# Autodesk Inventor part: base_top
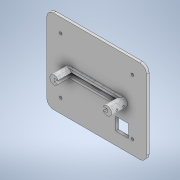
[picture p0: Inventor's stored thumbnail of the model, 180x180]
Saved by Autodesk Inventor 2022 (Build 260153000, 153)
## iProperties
Created: 2022-12
Part Number: base_top
Material: Generic
Document SubType Name: Modeling
Designer: suerfu
Density: 1 g/cm^3
Appearance: Default
Author: suerfu
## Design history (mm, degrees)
sketch "Sketch1"
  geometry: L1 (-47.625, 40.005)-(47.625, 40.005); L2 (47.625, 40.005)-(47.625, -40.005); L3 (47.625, -40.005)-(-47.625, -40.005); L4 (-47.625, -40.005)-(-47.625, 40.005); L5 (18.288, -15.748)-(30.48, -15.748); L6 (30.48, -15.748)-(30.48, -27.94); L7 (30.48, -27.94)-(18.288, -27.94); L8 (18.288, -27.94)-(18.288, -15.748); 1 further point
  constraints: 16 end point, 4 parallel, 2 horizontal, 2 perpendicular
  dimensions: "d0" = 95.25 distance of L2.end L3.end; "d1" = 80.01 distance of L3.end L1.start; "d29" = 47.625 distance from line of L4 point (0, 0) (= 0.5 x d0); "d30" = 40.005 distance from line of L3 point (0, 0) (= 0.5 x d1); "d42" = 18.288 distance from line of point (0, 0) L8; "d43" = 30.48 distance from line of point (0, 0) L6; "d44" = 15.748 distance from line of point (0, 0) L5; "d45" = 27.94 distance from line of L7 point (0, 0)
extrude "Extrusion1" new body sketch "Sketch1" distance "d26" = 2.54; taper "d27" = 0 deg
fillet "Fillet1" dims "d28" = 6.35
sketch "Sketch2"
  geometry: 5 further points
  constraints: 2 horizontal alignment, 2 vertical alignment
  dimensions: "d38" = 68.58 distance of point (34.29, 26.67) point (-34.29, 26.67); "d39" = 53.34 distance of point (-34.29, -26.67) point (-34.29, 26.67); "d40" = 34.29 horizontal distance of point (0, 0) point (-34.29, 26.67) (= 0.5 x d38); "d41" = 26.67 vertical distance of point (0, 0) point (-34.29, 26.67) (= 0.5 x d39)
hole "Hole1" sketch "Sketch2" at (-34.29, 26.67), (34.29, 26.67), (34.29, -26.67), (-34.29, -26.67) diameter "d31" = 2.4384; stored, may be unused: countersink angle "d35" = 82 deg, drill point angle "d37" = 118 deg; dims "d32" = 19.05, "d33" = 4.3688, "d34" = 6.35, "d36" = 12.7
sketch "Sketch3"
  geometry: L1 (-25.362, 1.626)-(-15.735, 1.626); L2 (-15.735, 1.626)-(-15.735, -1.626); L3 (-15.735, -1.626)-(-25.362, -1.626); L4 (-25.362, -1.626)-(-25.362, 1.626); L5 (-3.848, 1.626)-(3.848, 1.626); L6 (3.848, 1.626)-(3.848, -1.626); L7 (3.848, -1.626)-(-3.848, -1.626); L8 (-3.848, -1.626)-(-3.848, 1.626); L9 (15.735, 1.626)-(25.362, 1.626); L10 (25.362, 1.626)-(25.362, -1.626); L11 (25.362, -1.626)-(15.735, -1.626); L12 (15.735, -1.626)-(15.735, 1.626); L13 (-15.735, 0.909)-(15.735, 0.909); L14 (15.735, 0.909)-(15.735, -0.852); L15 (15.735, -0.852)-(-15.735, -0.852); L16 (-15.735, -0.852)-(-15.735, 0.909); 9 further points
  constraints: 32 end point, 8 parallel, 4 collinear, 4 horizontal, 4 perpendicular
  dimensions: "d46" = 9.6266 distance of L1.start L1.end; "d47" = 9.6266 distance of L9.start L9.end (= d46); "d48" = 7.6962 distance of L5.start L5.end; "d49" = 3.2512 distance of L3.end L1.start; "d50" = 3.2512 distance of L9.end L10.end (= d49); "d51" = 3.2512 distance of L5.end L6.end (= d49); "d52" = 11.8872 distance between parallel lines of L8 L2; "d53" = 11.8872 distance between parallel lines of L12 L6 (= d52); "d54" = 1.6256 distance from line of point (0, 0) L1 (= 0.5 x d49); "d55" = 3.8481 distance from line of point (0, 0) L6 (= 0.5 x d48); "d56" = 1.76097 distance between parallel lines of L15 L13
extrude "Extrusion2" cut sketch "Sketch3" distance "d57" = 2.54; taper "d58" = 0 deg
sketch "Sketch4"
  geometry: L1 (-25.362, -1.626)-(-25.362, 1.626) reference; L2 (15.735, -1.626)-(25.362, -1.626) reference; L3 (-25.362, 1.626)-(25.362, 1.626); L4 (25.362, 1.626)-(25.362, -1.626); L5 (25.362, -1.626)-(-25.362, -1.626); L6 (-25.362, -1.626)-(-25.362, 1.626); L7 (-25.362, 4.166)-(25.362, 4.166); L8 (25.362, -4.166)-(-25.362, -4.166); L9 (-25.362, 1.626)-(-25.362, -1.626) reference; L10 (-25.362, -1.626)-(-25.362, 1.626); L11 (25.362, -1.626)-(25.362, 1.626) reference; L12 (25.362, 1.626)-(25.362, -1.626); A1 r 4.166 centre (-25.362, 0) between (-25.362, 4.166) and (-25.362, -4.166); A2 r 4.166 centre (25.362, 0) between (25.362, -4.166) and (25.362, 4.166); 4 further points
  constraints: 16 end point, 5 point on circle, 3 parallel, 3 point on line, 2 centre point, 2 horizontal, 2 midpoint, 1 perpendicular, 1 tangent
  dimensions: "d59" = 2.54 distance between parallel lines of L3 L7; "d61" = 2.54 distance between parallel lines of L8 L5 (= d59)
extrude "Extrusion3" join sketch "Sketch4" distance "d63" = 2.54; taper "d64" = 0 deg
sketch "Sketch5"
  geometry: L1 (-25.362, 1.626)-(-25.362, -1.626) reference; L2 (25.362, -1.626)-(25.362, 1.626) reference; L3 (15.735, -1.626)-(25.362, -1.626) reference; L4 (25.362, 1.626)-(25.362, -1.626); L5 (-25.362, -1.626)-(-25.362, 1.626); L6 (-25.362, 1.626)-(-21.527, 1.626); L7 (21.527, 1.626)-(25.362, 1.626); L8 (25.362, -1.626)-(21.527, -1.626); L9 (-21.527, -1.626)-(-25.362, -1.626); A1 r 4.166 centre (-25.362, 0) between (-21.527, 1.626) and (-21.527, -1.626); A2 r 4.166 centre (25.362, 0) between (21.527, -1.626) and (21.527, 1.626); 4 further points
  constraints: 12 end point, 5 parallel, 4 point on circle, 2 centre point, 2 horizontal, 2 midpoint, 2 perpendicular
extrude "Extrusion4" join sketch "Sketch5" distance "d65" = 12.7; taper "d66" = 0 deg
sketch "Sketch6"
  geometry: L1 (0, -32.029)-(0, 35.281) reference; 4 further points
  constraints: 2 horizontal alignment, 1 midpoint
  dimensions: "d74" = 6.35 distance from line of L1 point (-6.35, 1.626); "d75" = 6.35 distance of point (-6.35, 1.626) point (-12.7, 1.626)
hole "Hole2" sketch "Sketch6" at (-12.7, 1.626), (-6.35, 1.626) diameter "d67" = 1.778; stored, may be unused: countersink angle "d71" = 82 deg, drill point angle "d73" = 118 deg; dims "d68" = 19.05, "d69" = 3.0226, "d70" = 6.35, "d72" = 12.7
sketch "Sketch7"
  geometry: L1 (0, 35.281)-(0, -32.029) reference; 4 further points
  constraints: 2 horizontal alignment, 1 midpoint
  dimensions: "d83" = 6.35 distance from line of point (6.35, 1.626) L1; "d84" = 6.35 distance of point (6.35, 1.626) point (12.7, 1.626)
hole "Hole3" sketch "Sketch7" at (12.7, 1.626), (6.35, 1.626) diameter "d76" = 1.778; stored, may be unused: countersink angle "d80" = 82 deg, drill point angle "d82" = 118 deg; dims "d77" = 19.05, "d78" = 9.525, "d79" = 6.35, "d81" = 25.4
body "Solid1"
other parameters: "d60" = 2.54 (= d59), "d62" = 2.54 (= d60)
